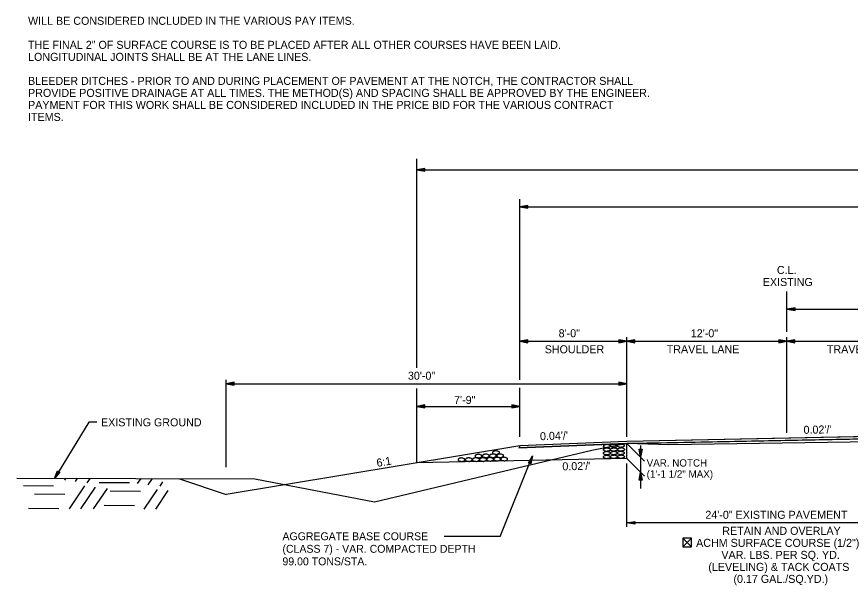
# Model space of a CAD drawing. Extents: x 1461846 to 1462006, y 1686171 to 1686805.
# Drawn here: x 1461849.8 to 1461912.3, y 1686445.2 to 1686487.8 of the extents above; entities that cross this region are included whole.
import ezdxf

# ---------------------------------------------------------------- set-up
doc = ezdxf.new("R2010")
doc.units = 0
for name, color, linetype in [('1', 7, 'Continuous'), ('10', 7, 'Continuous'), ('19', 7, 'Continuous'), ('20', 7, 'Continuous'), ('R_Draft', 7, 'Continuous')]:
    doc.layers.add(name, color=color, linetype=linetype)

# ---------------------------------------------------------------- blocks, each defined once
blk = doc.blocks.new('ROCKS')
at = {"layer": '1'}
blk.add_spline([(0.013, 0.06), (0.053, 0.053), (0.107, 0.033), (0.133, 0.013), (0.133, -0.007), (0.12, -0.033), (0.107, -0.04), (0.073, -0.053), (0.033, -0.067), (0.013, -0.067), (-0.02, -0.06), (-0.06, -0.053), (-0.087, -0.047), (-0.113, -0.02), (-0.113, -0.007), (-0.107, 0.02), (-0.087, 0.033), (-0.067, 0.047), (-0.033, 0.053), (-0.02, 0.06), (0.013, 0.06)], degree=3, dxfattribs=at)

msp = doc.modelspace()

# ---------------------------------------------------------------- linework, layer by layer
at = {"layer": '10'}
for p, q in [((1461900.367, 1686448.706), (1461899.726, 1686448.065)), ((1461899.726, 1686448.706), (1461900.367, 1686448.065))]:
    msp.add_line(p, q, dxfattribs=at)
msp.add_lwpolyline([(1461900.118, 1686448.065), (1461900.367, 1686448.065), (1461900.367, 1686448.706), (1461899.726, 1686448.706), (1461899.726, 1686448.065), (1461900.107, 1686448.065)], dxfattribs=at)
at = {"layer": '19'}
for p, q in [((1461887.514, 1686455.645), (1461887.429, 1686455.475)), ((1461896.454, 1686455.376), (1461896.664, 1686455.376)), ((1461896.559, 1686454.776), (1461896.454, 1686455.376)), ((1461896.544, 1686454.936), (1461896.504, 1686455.376)), ((1461896.664, 1686455.376), (1461896.559, 1686454.776)), ((1461896.609, 1686455.376), (1461896.574, 1686454.936)), ((1461886.044, 1686448.831), (1461888.468, 1686454.88)), ((1461888.148, 1686454.363), (1461888.468, 1686454.88)), ((1461888.195, 1686454.345), (1461888.394, 1686454.738)), ((1461888.42, 1686454.728), (1461888.293, 1686454.307)), ((1461888.468, 1686454.88), (1461888.341, 1686454.284)), ((1461888.341, 1686454.284), (1461888.148, 1686454.363)), ((1461853.413, 1686453.055), (1461853.519, 1686453.205)), ((1461854.207, 1686452.962), (1461854.374, 1686453.206)), ((1461855.102, 1686452.868), (1461855.329, 1686453.206)), ((1461858.866, 1686452.803), (1461859.129, 1686453.198)), ((1461859.661, 1686452.71), (1461859.994, 1686453.198)), ((1461896.454, 1686453.051), (1461896.559, 1686453.651)), ((1461896.509, 1686453.051), (1461896.544, 1686453.491)), ((1461896.559, 1686453.651), (1461896.664, 1686453.051)), ((1461896.574, 1686453.491), (1461896.614, 1686453.051)), ((1461850.315, 1686452.667), (1461852.575, 1686452.641)), ((1461853.76, 1686450.907), (1461854.916, 1686452.626)), ((1461855.99, 1686452.895), (1461858.251, 1686452.878)), ((1461860.556, 1686452.616), (1461860.772, 1686452.94)), ((1461896.664, 1686453.051), (1461896.454, 1686453.051)), ((1461851.154, 1686452.036), (1461853.413, 1686452.01)), ((1461854.614, 1686450.908), (1461855.71, 1686452.532)), ((1461855.57, 1686450.908), (1461856.605, 1686452.438)), ((1461856.819, 1686452.265), (1461859.089, 1686452.247)), ((1461859.37, 1686450.9), (1461860.369, 1686452.374)), ((1461860.225, 1686450.901), (1461861.164, 1686452.28)), ((1461850.698, 1686450.958), (1461852.969, 1686450.94)), ((1461856.374, 1686451.195), (1461858.634, 1686451.169)), ((1461886.044, 1686448.831), (1461881.834, 1686448.831))]:
    msp.add_line(p, q, dxfattribs=at)
msp.add_lwpolyline([(1461887.429, 1686455.475), (1461895.514, 1686455.798), (1461925.014, 1686456.388), (1461954.514, 1686455.798), (1461962.599, 1686455.475), (1461962.514, 1686455.645), (1461954.514, 1686455.965), (1461925.014, 1686456.555), (1461895.514, 1686455.965), (1461887.514, 1686455.645)], close=True, dxfattribs=at)
at = {"layer": '20'}
for p, q in [((1461879.798, 1686464.782), (1461879.798, 1686477.131)), ((1461880.398, 1686476.412), (1461879.798, 1686476.307)), ((1461880.398, 1686476.357), (1461879.958, 1686476.322)), ((1461880.398, 1686476.202), (1461880.398, 1686476.412)), ((1461879.798, 1686476.307), (1461970.238, 1686476.307)), ((1461879.798, 1686476.307), (1461880.398, 1686476.202)), ((1461879.958, 1686476.292), (1461880.398, 1686476.252)), ((1461887.514, 1686464.782), (1461887.514, 1686474.105)), ((1461888.114, 1686473.642), (1461887.514, 1686473.537)), ((1461887.514, 1686473.537), (1461962.514, 1686473.537)), ((1461887.514, 1686473.537), (1461888.114, 1686473.432)), ((1461888.114, 1686473.587), (1461887.674, 1686473.552)), ((1461887.674, 1686473.522), (1461888.114, 1686473.482)), ((1461888.114, 1686473.432), (1461888.114, 1686473.642)), ((1461879.798, 1686461.48), (1461879.798, 1686464.782)), ((1461887.514, 1686463.765), (1461887.514, 1686464.782)), ((1461879.798, 1686454.359), (1461879.798, 1686459.93)), ((1461880.398, 1686458.693), (1461879.798, 1686458.588)), ((1461879.798, 1686458.588), (1461887.514, 1686458.588)), ((1461879.798, 1686458.588), (1461880.398, 1686458.483)), ((1461880.398, 1686458.638), (1461879.958, 1686458.603)), ((1461879.958, 1686458.573), (1461880.398, 1686458.533)), ((1461880.398, 1686458.483), (1461880.398, 1686458.693)), ((1461886.914, 1686458.693), (1461886.914, 1686458.483)), ((1461887.514, 1686458.588), (1461886.914, 1686458.693)), ((1461887.354, 1686458.603), (1461886.914, 1686458.638)), ((1461886.914, 1686458.483), (1461887.514, 1686458.588)), ((1461886.914, 1686458.533), (1461887.354, 1686458.573)), ((1461895.514, 1686455.798), (1461896.797, 1686454.543)), ((1461895.514, 1686455.798), (1461896.858, 1686454.483)), ((1461895.514, 1686454.673), (1461896.858, 1686453.358))]:
    msp.add_line(p, q, dxfattribs=at)
msp.add_lwpolyline([(1461896.559, 1686455.652), (1461896.559, 1686452.442)], dxfattribs=at)
at = {"layer": 'R_Draft'}
for p, q in [((1461907.514, 1686464.173), (1461907.514, 1686467.196)), ((1461907.514, 1686465.864), (1461925.014, 1686465.864)), ((1461908.143, 1686465.969), (1461907.543, 1686465.864)), ((1461907.543, 1686465.864), (1461908.143, 1686465.759)), ((1461908.143, 1686465.914), (1461907.703, 1686465.879)), ((1461907.703, 1686465.849), (1461908.143, 1686465.809)), ((1461908.143, 1686465.759), (1461908.143, 1686465.969)), ((1461887.514, 1686460.586), (1461887.514, 1686463.765)), ((1461888.114, 1686463.57), (1461887.514, 1686463.465)), ((1461887.514, 1686463.465), (1461895.514, 1686463.465)), ((1461887.514, 1686463.465), (1461888.114, 1686463.36)), ((1461888.114, 1686463.515), (1461887.674, 1686463.48)), ((1461887.674, 1686463.45), (1461888.114, 1686463.41)), ((1461888.114, 1686463.36), (1461888.114, 1686463.57)), ((1461894.914, 1686463.57), (1461894.914, 1686463.36)), ((1461895.514, 1686463.465), (1461894.914, 1686463.57)), ((1461895.354, 1686463.48), (1461894.914, 1686463.515)), ((1461894.914, 1686463.36), (1461895.514, 1686463.465)), ((1461894.914, 1686463.41), (1461895.354, 1686463.45)), ((1461895.514, 1686456.295), (1461895.514, 1686463.765)), ((1461896.114, 1686463.57), (1461895.514, 1686463.465)), ((1461896.114, 1686463.57), (1461895.514, 1686463.465)), ((1461895.514, 1686463.465), (1461896.114, 1686463.36)), ((1461895.514, 1686463.465), (1461907.514, 1686463.465)), ((1461895.514, 1686463.465), (1461896.114, 1686463.36)), ((1461896.114, 1686463.515), (1461895.674, 1686463.48)), ((1461896.114, 1686463.515), (1461895.674, 1686463.48)), ((1461895.674, 1686463.45), (1461896.114, 1686463.41)), ((1461895.674, 1686463.45), (1461896.114, 1686463.41)), ((1461896.114, 1686463.36), (1461896.114, 1686463.57)), ((1461896.114, 1686463.36), (1461896.114, 1686463.57)), ((1461906.914, 1686463.57), (1461906.914, 1686463.36)), ((1461907.514, 1686463.465), (1461906.914, 1686463.57)), ((1461907.354, 1686463.48), (1461906.914, 1686463.515)), ((1461906.914, 1686463.36), (1461907.514, 1686463.465)), ((1461906.914, 1686463.41), (1461907.354, 1686463.45)), ((1461907.514, 1686456.615), (1461907.514, 1686463.765)), ((1461908.114, 1686463.57), (1461907.514, 1686463.465)), ((1461907.514, 1686463.465), (1461919.514, 1686463.465)), ((1461907.514, 1686463.465), (1461908.114, 1686463.36)), ((1461908.114, 1686463.515), (1461907.674, 1686463.48)), ((1461907.674, 1686463.45), (1461908.114, 1686463.41)), ((1461908.114, 1686463.36), (1461908.114, 1686463.57)), ((1461865.514, 1686454.042), (1461865.514, 1686460.586)), ((1461866.114, 1686460.391), (1461865.514, 1686460.286)), ((1461865.514, 1686460.286), (1461895.514, 1686460.286)), ((1461865.514, 1686460.286), (1461866.114, 1686460.181)), ((1461866.114, 1686460.336), (1461865.674, 1686460.301)), ((1461865.674, 1686460.271), (1461866.114, 1686460.231)), ((1461866.114, 1686460.181), (1461866.114, 1686460.391)), ((1461894.914, 1686460.391), (1461894.914, 1686460.181)), ((1461895.514, 1686460.286), (1461894.914, 1686460.391)), ((1461895.354, 1686460.301), (1461894.914, 1686460.336)), ((1461894.914, 1686460.181), (1461895.514, 1686460.286)), ((1461894.914, 1686460.231), (1461895.354, 1686460.271)), ((1461887.514, 1686456.295), (1461887.514, 1686459.986)), ((1461925.014, 1686456.555), (1461895.514, 1686455.965)), ((1461925.014, 1686456.388), (1461898.514, 1686455.858)), ((1461895.514, 1686455.798), (1461887.429, 1686455.475)), ((1461895.514, 1686455.965), (1461887.514, 1686455.645)), ((1461898.514, 1686455.858), (1461895.514, 1686455.798)), ((1461895.514, 1686454.673), (1461895.514, 1686455.798)), ((1461887.514, 1686455.645), (1461865.514, 1686451.978)), ((1461895.514, 1686454.673), (1461879.798, 1686454.359)), ((1461895.514, 1686449.567), (1461895.514, 1686454.316)), ((1461852.645, 1686453.195), (1461852.868, 1686453.762)), ((1461853.046, 1686453.652), (1461852.645, 1686453.195)), ((1461852.718, 1686453.336), (1461852.911, 1686453.729)), ((1461853.005, 1686453.673), (1461852.741, 1686453.325)), ((1461852.868, 1686453.762), (1461853.046, 1686453.652)), ((1461861.998, 1686453.15), (1461865.514, 1686451.978)), ((1461895.514, 1686449.867), (1461896.114, 1686449.972)), ((1461919.514, 1686449.867), (1461895.514, 1686449.867)), ((1461896.114, 1686449.762), (1461895.514, 1686449.867)), ((1461895.674, 1686449.882), (1461896.114, 1686449.917)), ((1461896.114, 1686449.812), (1461895.674, 1686449.852)), ((1461896.114, 1686449.972), (1461896.114, 1686449.762))]:
    msp.add_line(p, q, dxfattribs=at)
for points in [[(1461855.827, 1686457.394), (1461855.227, 1686457.394), (1461852.645, 1686453.195)], [(1461950.863, 1686448.051), (1461926.446, 1686454.761), (1461919.514, 1686456.278), (1461917.357, 1686455.991), (1461898.673, 1686455.704), (1461895.514, 1686455.798), (1461892.913, 1686455.285), (1461876.611, 1686451.414), (1461867.661, 1686453.131), (1461849.809, 1686453.192)]]:
    msp.add_lwpolyline(points, dxfattribs=at)

# ---------------------------------------------------------------- block references
at = {"layer": '19', "xscale": 2.061136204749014}
for p, yscale, rotation in [((1461894.04, 1686455.623), -2.061136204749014, -179.20800457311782), ((1461894.571, 1686455.646), -2.061136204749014, -179.20800457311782), ((1461895.093, 1686455.653), -2.061136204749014, -179.20800457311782), ((1461885.7, 1686455.133), 2.0611362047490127, 0.2099095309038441), ((1461894.04, 1686455.093), -2.061136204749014, -179.20800457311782), ((1461894.044, 1686455.356), -2.061136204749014, -179.20800457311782), ((1461894.571, 1686455.1), -2.061136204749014, -179.20800457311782), ((1461894.575, 1686455.363), -2.061136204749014, -179.20800457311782), ((1461895.093, 1686455.107), -2.061136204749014, -179.20800457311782), ((1461895.108, 1686455.371), -2.061136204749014, -179.20800457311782), ((1461883.118, 1686454.603), 2.0611362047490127, 0.2099095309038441), ((1461883.657, 1686454.605), 2.0611362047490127, 0.2099095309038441), ((1461884.201, 1686454.607), 2.0611362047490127, 0.2099095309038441), ((1461884.394, 1686454.873), 2.0611362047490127, 0.2099095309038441), ((1461884.728, 1686454.609), 2.0611362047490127, 0.2099095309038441), ((1461884.937, 1686454.891), 2.0611362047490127, 0.2099095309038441), ((1461885.259, 1686454.626), 2.0611362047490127, 0.2099095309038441), ((1461885.47, 1686454.893), 2.0611362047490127, 0.2099095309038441), ((1461885.783, 1686454.64), 2.0611362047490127, 0.2099095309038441), ((1461886.013, 1686454.895), 2.0611362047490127, 0.2099095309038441), ((1461886.316, 1686454.652), 2.0611362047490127, 0.2099095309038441), ((1461894.044, 1686454.81), -2.061136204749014, -179.20800457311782), ((1461894.575, 1686454.818), -2.061136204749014, -179.20800457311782), ((1461895.108, 1686454.825), -2.061136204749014, -179.20800457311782)]:
    msp.add_blockref('ROCKS', p, dxfattribs=dict(at, yscale=yscale, rotation=rotation))

# ---------------------------------------------------------------- texts
at = {"layer": '10'}
for s, p in [('VAR. NOTCH', (1461897.008, 1686454.079)), ('(1\'-1 1/2" MAX)', (1461897.008, 1686453.25))]:
    msp.add_text(s, height=0.55, dxfattribs=at).set_placement(p)
at = {"layer": '19'}
for s, p in [('AGGREGATE BASE COURSE', (1461869.722, 1686448.565)), ('(CLASS 7) - VAR. COMPACTED DEPTH', (1461869.722, 1686447.625)), ('99.00 TONS/STA.', (1461869.722, 1686446.685))]:
    msp.add_text(s, height=0.59001, rotation=360, dxfattribs=at).set_placement(p)
at = {"layer": 'R_Draft'}
for s, p in [('WILL BE CONSIDERED INCLUDED IN THE VARIOUS PAY ITEMS.', (1461850.662, 1686487.167)), ('THE FINAL 2" OF SURFACE COURSE IS TO BE PLACED AFTER ALL OTHER COURSES HAVE BEEN LAID. ', (1461850.662, 1686485.367)), ('LONGITUDINAL JOINTS SHALL BE AT THE LANE LINES.', (1461850.662, 1686484.467)), ('BLEEDER DITCHES - PRIOR TO AND DURING PLACEMENT OF PAVEMENT AT THE NOTCH, THE CONTRACTOR SHALL ', (1461850.662, 1686482.667)), ('PROVIDE POSITIVE DRAINAGE AT ALL TIMES. THE METHOD(S) AND SPACING SHALL BE APPROVED BY THE ENGINEER. ', (1461850.662, 1686481.767)), ('PAYMENT FOR THIS WORK SHALL BE CONSIDERED INCLUDED IN THE PRICE BID FOR THE VARIOUS CONTRACT ', (1461850.662, 1686480.867)), ('ITEMS.', (1461850.662, 1686479.967)), ('C.L.', (1461906.768, 1686468.503)), ('EXISTING', (1461905.712, 1686467.603)), ('24\'-0" EXISTING PAVEMENT', (1461901.408, 1686450.167)), ('RETAIN AND OVERLAY', (1461902.676, 1686448.967)), ('ACHM SURFACE COURSE (1/2")', (1461900.716, 1686448.067)), ('VAR. LBS. PER SQ. YD.', (1461902.61, 1686447.167)), ('(LEVELING) & TACK COATS', (1461901.632, 1686446.267)), ('(0.17 GAL./SQ.YD.)', (1461903.513, 1686445.367))]:
    msp.add_text(s, height=0.6, dxfattribs=at).set_placement(p)
for s, rotation, p in [('8\'-0"', 360, (1461890.416, 1686463.765)), ('12\'-0"', 360, (1461900.317, 1686463.765)), ('SHOULDER', 360, (1461889.372, 1686462.565)), ('TRAVEL LANE', 360, (1461898.514, 1686462.565)), ('TRAVEL LANE', 360, (1461910.514, 1686462.565)), ('30\'-0"', 360, (1461879.123, 1686460.586)), ('7\'-9"', 360, (1461882.581, 1686458.771)), ('EXISTING GROUND', 360, (1461856.127, 1686457.094)), ("0.02'/'", 1.14576, (1461908.77, 1686456.53)), ("0.04'/'", 2.16019, (1461889.03, 1686456.049)), ('6:1', 9.26751, (1461876.818, 1686454.052)), ("0.02'/'", 1.14576, (1461890.699, 1686453.795))]:
    msp.add_text(s, height=0.6, rotation=rotation, dxfattribs=at).set_placement(p)

doc.saveas('drawing.dxf')
